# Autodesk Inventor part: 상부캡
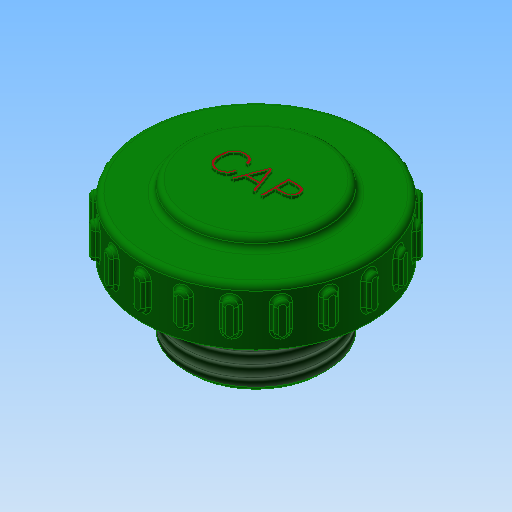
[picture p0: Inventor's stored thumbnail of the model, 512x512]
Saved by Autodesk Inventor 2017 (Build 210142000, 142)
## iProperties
Created: 2015-12
Part Number: 상부캡
Material: PC/ABS 플라스틱
Document SubType Name: Modeling
Designer: mduedu
Density: 7.86 g/cm^3
Appearance: 진녹색
Author: mduedu
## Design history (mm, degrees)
sketch "스케치1"
  geometry: C1 r 12.5 at (0, 0); C2 r 8 at (0, 0); 1 further point
  constraints: 2 centre point, 2 coincident
  dimensions: "d1" = 25 diameter of C1; "d3" = 16 diameter of C2
extrude "돌출1" new body sketch "스케치1" distance "d4" = 12; taper "d6" = 0 deg; dims "d5" = 12, "d7" = 0
sketch "스케치2"
  geometry: C1 r 20 at (0, 0); C2 r 12.5 at (0, 0) reference; 1 further point
  constraints: 1 centre point, 1 coincident
  dimensions: "d8" = 40 diameter of C1
extrude "돌출2" join sketch "스케치2" distance "d10" = 10; taper "d11" = 0 deg
extrude "돌출3" cut sketch "스케치1" stored distance "d34" = 10; taper "d35" = 0 deg
sketch "스케치5"
  geometry: L1 (-20, 0)-(-20, 10) reference; L2 (-20, 10)-(-12.5, 10) reference; L3 (-12.5, 10)-(-12.5, 12) reference; L4 (-12.5, 12)-(12.5, 12) reference; L5 (12.5, 12)-(12.5, 10) reference; L6 (12.5, 10)-(20, 10) reference; L7 (20, 10)-(20, 0) reference; L8 (20, 0)-(12.5, 0) reference; L9 (12.5, 0)-(12.5, -12) reference; L10 (12.5, -12)-(8, -12) reference; L11 (8, -12)-(8, 0) reference; L12 (8, 0)-(-8, 0) reference; L13 (-8, 0)-(-8, -12) reference; L14 (-8, -12)-(-12.5, -12) reference; L15 (-12.5, -12)-(-12.5, 0) reference; L16 (-12.5, 0)-(-20, 0) reference; L17 (12.5, 0)-(10.5, 0); L18 (10.5, 0)-(10.5, -1); L19 (10.5, -1)-(12.5, -1); L20 (12.5, -1)-(12.5, 0); 2 further points
  constraints: 8 end point, 2 parallel, 1 horizontal, 1 midpoint, 1 perpendicular, 1 vertical alignment, 2 other
  dimensions: "d36" = 2 distance of L19.end L18.end; "d37" = 1 distance of L18.end L17.end
revolve "회전1" sketch "스케치5" stored, may be unused: angle "d38" = 90 deg
feature "스레드1" dims "d39" = 10, "d40" = 0
chamfer "모따기3" distance "d41" = 1; stored, may be unused: second distance "d42" = 2, angle "d43" = 45 deg
fillet "모깎기4" dims "d44" = 3
node "작업 평면1"
sketch "스케치7"
  geometry: L1 (1, 0)-(-1, 0); L2 (-1, 0)-(-1, 20.976); L3 (1, 20.976)-(1, 0); C1 r 20 at (0, 0) reference; A1 r 21 centre (0, 0) between (1, 20.976) and (-1, 20.976); 2 further points
  constraints: 6 end point, 2 coincident, 2 point on circle, 1 centre point, 1 horizontal, 1 midpoint, 1 parallel, 1 perpendicular
  dimensions: "d48" = 2 distance of L1.start L1.end; "d49" = 1 radial gap between concentric circles of A1 C1
extrude "돌출4" join sketch "스케치7" distance "d50" = 3; taper "d52" = 0 deg; dims "d51" = 3, "d53" = 0
fillet "모깎기5" dims "d54" = 1
fillet "모깎기6" dims "d55" = 0.5
fillet "모깎기7" dims "d59" = 1
sketch "스케치8"
  geometry: 2 further points
  constraints: 1 coincident, 1 other
feature "엠보싱1" sketch "스케치8" dims "d60" = 0.5, "d61" = 0
node "솔리드1"
pattern_circular "원형 패턴1" dims angle "d57" = 360 deg
node "절단 모서리 투영1"
node "절단 모서리 투영3"
